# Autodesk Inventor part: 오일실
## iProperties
IsCustomPart: 1
Created: 2015-10
Part Number: 오일실
Material: 고무
Description: 오일-실
Document SubType Name: Modeling
Standard: KS B 2804
Designer: mdu
Standards Organization: KS
Language: ko-KR
Size Designation: S - 25 38 8
Categories: <MemberInstance><Categories><Category DisplayName="샤프트 부품" InternalName="7f7aeb1f-a693-4053-b835-cee3144e0d98" Mnemonic="SHFT"><Category DisplayName="실링" Intern
Density: 0.93 g/cm^3
Author: mdu
